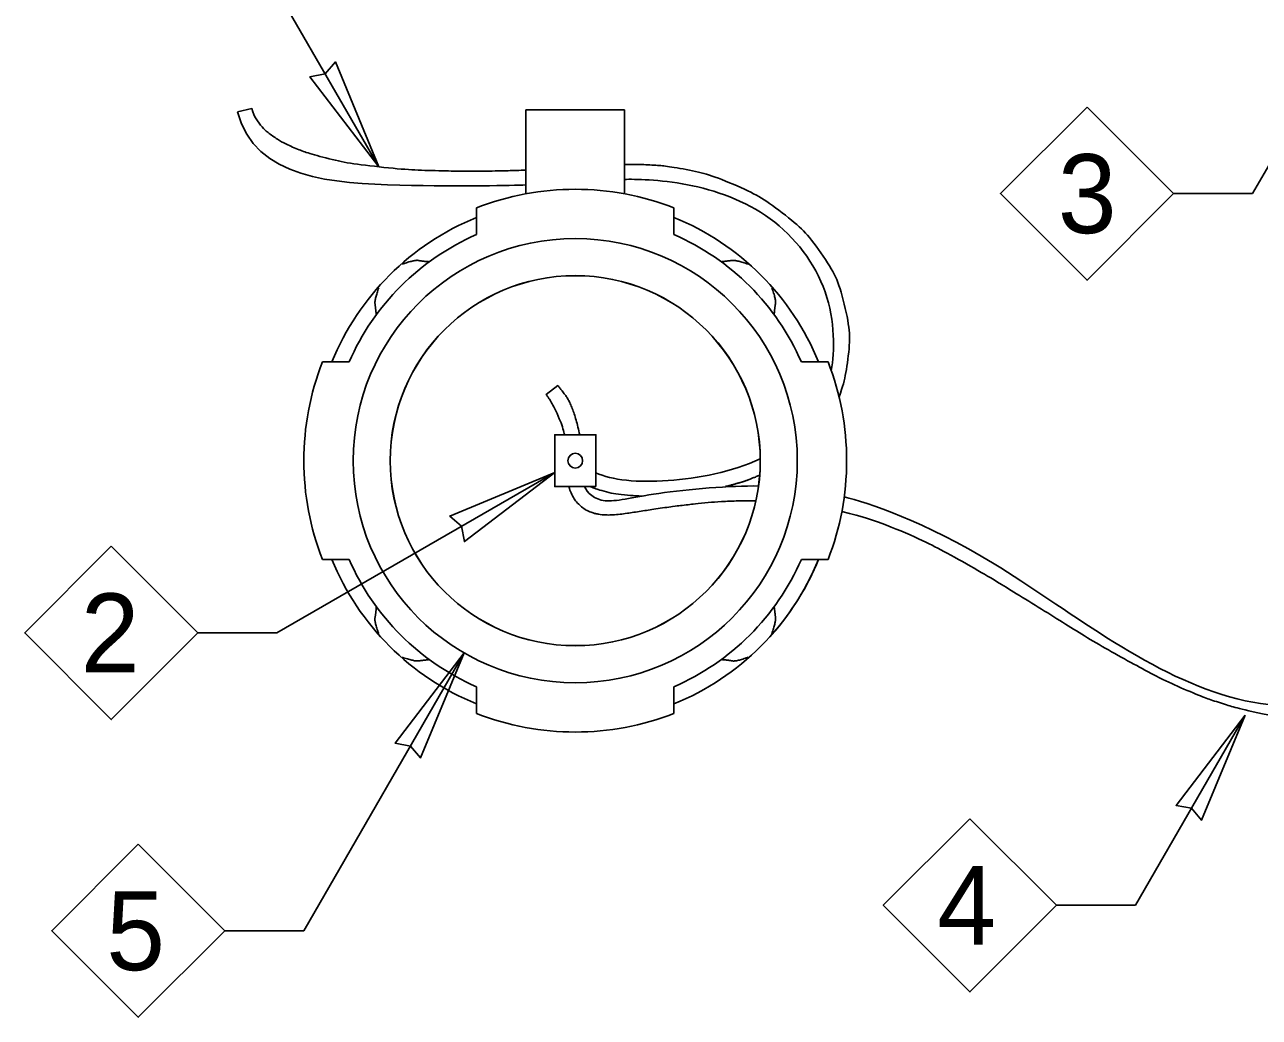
# Model space of a CAD drawing. Extents: x 99862 to 103680, y 99470 to 102076.
# Drawn here: x 100185.9 to 100436.1, y 100212.4 to 100413.6 of the extents above; entities that cross this region are included whole.
import ezdxf

# ---------------------------------------------------------------- set-up
doc = ezdxf.new("R2010")
doc.units = 0
for name, color, linetype in [('Level 1', 7, 'Continuous'), ('Level 11', 7, 'Continuous'), ('Level 15', 7, 'Continuous'), ('Level 20', 7, 'Continuous'), ('Level 3', 7, 'Continuous'), ('Level 4', 7, 'Continuous'), ('Level 5', 7, 'Continuous'), ('Level 8', 7, 'Continuous'), ('Level 9', 7, 'Continuous')]:
    doc.layers.add(name, color=color, linetype=linetype)

msp = doc.modelspace()

# ---------------------------------------------------------------- linework, layer by layer
at = {"layer": 'Level 1'}
msp.add_circle((100297.48, 100325.26), 37.49, dxfattribs=at)
at = {"layer": 'Level 11'}
for points in [[(100510.88, 100391.91), (100510.88, 100423.45), (100465.8, 100458.51), (100384.44, 100444.44), (100299.25, 100431.66), (100238.45, 100476.01), (100238.63, 100499.41)], [(100250.4, 100499.41), (100251.03, 100487.36), (100262.3, 100450.41), (100309.58, 100418.45), (100364.95, 100427.4), (100409.25, 100437.62), (100437.58, 100442.78), (100465.99, 100438.02), (100487.69, 100421.82), (100494.02, 100413.33), (100505.7, 100388.64)]]:
    msp.add_open_spline(points, degree=3, dxfattribs=at)
at = {"layer": 'Level 15'}
for p, q in [((100257.7, 100384.8), (100225.2, 100441.1)), ((100467.24, 100435.67), (100434.74, 100379.38)), ((100418.74, 100379.38), (100434.74, 100379.38)), ((100293.31, 100322.85), (100237.02, 100290.35)), ((100221.02, 100290.35), (100237.02, 100290.35)), ((100274.98, 100286.29), (100242.48, 100230)), ((100433.24, 100273.67), (100411, 100235.14)), ((100395, 100235.14), (100411, 100235.14)), ((100226.48, 100230), (100242.48, 100230))]:
    msp.add_line(p, q, dxfattribs=at)
for points in [[(100257.7, 100384.8), (100243.7, 100403.08), (100246.82, 100403.66), (100248.87, 100406.07)], [(100293.31, 100322.85), (100275.03, 100308.85), (100274.45, 100311.96), (100272.04, 100314.02)], [(100274.98, 100286.29), (100260.98, 100268.01), (100264.1, 100267.43), (100266.15, 100265.03)], [(100433.24, 100273.67), (100419.24, 100255.39), (100422.36, 100254.81), (100424.41, 100252.4)]]:
    msp.add_lwpolyline(points, close=True, dxfattribs=at)
at = {"layer": 'Level 20'}
for points in [[(100401.19, 100396.93), (100418.74, 100379.38), (100401.19, 100361.82), (100383.63, 100379.38)], [(100203.46, 100307.9), (100221.02, 100290.35), (100203.46, 100272.8), (100185.91, 100290.35)], [(100377.45, 100252.69), (100395, 100235.14), (100377.45, 100217.58), (100359.89, 100235.14)], [(100208.93, 100247.55), (100226.48, 100230), (100208.93, 100212.44), (100191.38, 100230)]]:
    msp.add_lwpolyline(points, close=True, dxfattribs=at)
at = {"layer": 'Level 3'}
msp.add_lwpolyline([(100301.66, 100320.02), (100293.31, 100320.02), (100293.31, 100330.5), (100301.66, 100330.5)], close=True, dxfattribs=at)
at = {"layer": 'Level 4'}
for p, q in [((100277.48, 100376.5), (100277.48, 100371.09)), ((100317.48, 100371.09), (100317.48, 100376.5)), ((100251.66, 100345.26), (100246.25, 100345.26)), ((100348.72, 100345.26), (100343.31, 100345.26)), ((100246.25, 100305.26), (100251.66, 100305.26)), ((100343.31, 100305.26), (100348.72, 100305.26)), ((100277.48, 100279.43), (100277.48, 100274.03)), ((100317.48, 100274.03), (100317.48, 100279.43))]:
    msp.add_line(p, q, dxfattribs=at)
for radius in [45, 37.5]:
    msp.add_circle((100297.48, 100325.26), radius, dxfattribs=at)
for radius, start, end in [(55, 68.6763, 111.3237), (50, 113.5782, 156.4218), (50, 23.5782, 66.4218), (55, 158.6763, 201.3237), (55, 338.6763, 21.3237), (50, 203.5782, 246.4218), (50, 293.5782, 336.4218), (55, 248.6763, 291.3237)]:
    msp.add_arc((100297.48, 100325.26), radius, start, end, dxfattribs=at)
at = {"layer": 'Level 5'}
for start, end in [(112.0844, 157.9156), (22.0844, 67.9156), (202.0844, 247.9156), (292.0844, 337.9156), (318.4957, 337.9156)]:
    msp.add_arc((100297.48, 100325.26), 53.2, start, end, dxfattribs=at)
for points in [[(100267.91, 100365.58), (100266.36, 100365.69), (100264.96, 100366), (100262.43, 100365.09)], [(100332.54, 100365.09), (100330.07, 100365.95), (100328.55, 100365.75), (100327.06, 100365.58)], [(100257.66, 100360.32), (100256.8, 100357.84), (100256.99, 100356.32), (100257.17, 100354.84)], [(100337.8, 100354.84), (100337.91, 100356.39), (100338.23, 100357.79), (100337.31, 100360.32)], [(100257.17, 100295.68), (100257.06, 100294.13), (100256.74, 100292.73), (100257.66, 100290.2)], [(100337.31, 100290.2), (100338.17, 100292.68), (100337.98, 100294.2), (100337.8, 100295.68)], [(100262.43, 100285.43), (100264.9, 100284.57), (100266.42, 100284.77), (100267.91, 100284.95)], [(100327.06, 100284.95), (100328.61, 100284.83), (100330.01, 100284.52), (100332.54, 100285.43)]]:
    msp.add_open_spline(points, degree=2, dxfattribs=at)
at = {"layer": 'Level 8'}
for p, q in [((100307.48, 100396.4), (100287.48, 100396.4)), ((100287.48, 100379.34), (100287.48, 100396.4)), ((100307.48, 100379.34), (100307.48, 100396.4))]:
    msp.add_line(p, q, dxfattribs=at)
at = {"layer": 'Level 9'}
for p, q in [((100229.05, 100395.95), (100231.96, 100396.67)), ((100293.96, 100340.49), (100291.58, 100338.67))]:
    msp.add_line(p, q, dxfattribs=at)
msp.add_circle((100297.48, 100325.26), 1.5, dxfattribs=at)
for points, degree in [([(100231.96, 100396.67), (100232.23, 100395.58), (100232.71, 100394.61), (100234.08, 100392.76), (100235, 100391.89), (100237.28, 100390.26), (100238.65, 100389.5), (100241.75, 100388.15), (100243.49, 100387.55), (100249.09, 100386), (100253.35, 100385.28), (100262.13, 100384.32), (100266.66, 100384.09), (100273.09, 100383.94), (100275.18, 100383.93), (100279.15, 100383.94), (100281.03, 100383.96), (100284.44, 100384.04), (100286, 100384.09), (100287.48, 100384.15)], 3), ([(100229.05, 100395.95), (100232.46, 100382.31), (100265.27, 100380.54), (100284.64, 100381.04), (100287.48, 100381.15)], 3), ([(100307.48, 100385.27), (100309.18, 100385.31), (100310.83, 100385.3), (100314.43, 100385.12), (100316.39, 100384.9), (100322.18, 100383.91), (100325.95, 100382.81), (100333.06, 100379.78), (100336.4, 100377.85), (100342.43, 100373.22), (100345.11, 100370.51), (100349.45, 100364.3), (100351.1, 100360.8), (100352.98, 100353.14), (100353.2, 100348.97), (100352.31, 100342.6), (100351.75, 100340.36), (100350.94, 100338.21)], 3), ([(100307.48, 100382.27), (100309.43, 100382.32), (100319.74, 100382.22), (100338, 100375.89), (100350.14, 100359.96), (100350.12, 100347.3), (100349.36, 100343.54)], 3), ([(100298.4, 100330.5), (100297.07, 100336.47), (100293.96, 100340.49), (100293.96, 100340.49)], 2), ([(100295.32, 100330.5), (100295.31, 100330.51), (100295.31, 100330.52), (100294.9, 100332.15), (100294.34, 100333.61), (100293.23, 100336.04), (100292.67, 100337.01), (100292.05, 100338.01), (100291.87, 100338.26), (100291.7, 100338.51), (100291.65, 100338.57), (100291.61, 100338.63), (100291.6, 100338.64), (100291.59, 100338.66), (100291.59, 100338.66), (100291.58, 100338.67)], 3), ([(100351.51, 100314.94), (100355.81, 100313.9), (100360.35, 100312.41), (100368.58, 100308.78), (100372.21, 100306.9), (100379.67, 100302.71), (100383.49, 100300.4), (100395.08, 100293.27), (100402.99, 100288.21), (100414.73, 100281.81), (100418.63, 100279.88), (100424.41, 100277.48), (100426.33, 100276.76), (100430.13, 100275.53), (100432.02, 100275.02), (100441.32, 100272.92), (100448.45, 100272.78), (100461.87, 100275.11), (100468.16, 100277.56), (100476.89, 100282.72), (100479.69, 100284.68), (100485.05, 100289.03), (100487.61, 100291.43), (100494.72, 100299.21), (100498.72, 100305.18), (100502.8, 100315.01), (100503.83, 100318.44), (100505.12, 100325.52), (100505.37, 100329.17), (100505.15, 100332.9)], 3), ([(100351.99, 100317.91), (100356.53, 100316.82), (100379.84, 100309.22), (100429.98, 100268.56), (100480.67, 100280.92), (100503.25, 100314.16), (100502.15, 100332.72)], 3), ([(100334.98, 100325.65), (100329.3, 100323.01), (100315.51, 100320.26), (100304.82, 100321.32), (100301.66, 100322.81)], 3), ([(100334.87, 100322.32), (100332.62, 100321.37), (100330.27, 100320.62), (100327.9, 100320.01)], 2), ([(100296.19, 100320.02), (100296.35, 100319.39), (100296.58, 100318.78), (100297.28, 100317.45), (100297.8, 100316.76), (100299.09, 100315.6), (100299.85, 100315.14), (100301.07, 100314.67), (100301.49, 100314.55), (100302.34, 100314.38), (100302.76, 100314.32), (100304.04, 100314.23), (100304.89, 100314.26), (100306.72, 100314.42), (100307.69, 100314.55), (100310.94, 100315.02), (100313.56, 100315.46), (100317.75, 100316.03), (100318.64, 100316.14), (100320.51, 100316.36), (100321.49, 100316.48), (100324.57, 100316.79), (100326.81, 100316.98), (100330.77, 100317.13), (100332.4, 100317.16), (100334.09, 100317.13)], 3), ([(100299.35, 100320.02), (100299.89, 100318.72), (100302.8, 100316.03), (100311.46, 100318.67), (100329.06, 100320.24), (100334.63, 100320.12)], 3), ([(100311.1, 100318.09), (100309.95, 100318.12), (100308.84, 100318.19), (100306.03, 100318.47), (100304.41, 100318.75), (100302.21, 100319.37), (100301.51, 100319.6), (100300.74, 100319.93), (100300.64, 100319.97), (100300.54, 100320.02)], 3)]:
    msp.add_open_spline(points, degree=degree, dxfattribs=at)

# ---------------------------------------------------------------- texts
at = {"layer": 'Level 20'}
for s, p in [('3', (100395.28, 100371.38)), ('2', (100197.28, 100282.35)), ('4', (100370.85, 100227.14)), ('5', (100202.44, 100222))]:
    msp.add_text(s, height=16, dxfattribs=at).set_placement(p)

doc.saveas('drawing.dxf')
